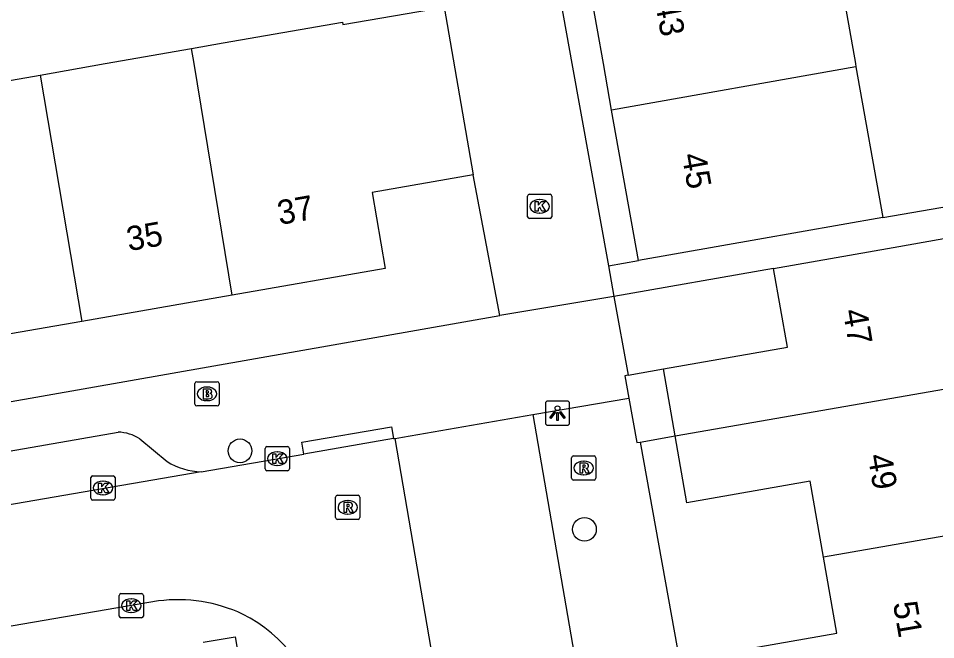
# Model space of a CAD drawing. Extents: x 162880 to 165536, y 384011 to 385179.
# Drawn here: x 164396.22 to 164434.07, y 384476.23 to 384501.87 of the extents above; entities that cross this region are included whole.
import ezdxf

# ---------------------------------------------------------------- set-up
doc = ezdxf.new("R2010")
doc.units = 0
for name, color, linetype in [('IMGEO_Boom', 7, 'Continuous'), ('IMGEO_Brandkraan', 7, 'Continuous'), ('IMGEO_Kolk', 7, 'Continuous'), ('IMGEO_Lichtpunt', 7, 'Continuous'), ('IMGEO_Pand', 7, 'Continuous'), ('IMGEO_Pand_nummerreeks', 7, 'Continuous'), ('IMGEO_Rijbaan_lokaal_open', 7, 'Continuous'), ('IMGEO_Rioolput', 7, 'Continuous'), ('IMGEO_Voetpad_open', 7, 'Continuous')]:
    doc.layers.add(name, color=color, linetype=linetype)

msp = doc.modelspace()

# ---------------------------------------------------------------- linework, layer by layer
at = {"layer": 'IMGEO_Boom'}
for centre in [(164405.369, 384484.024), (164419.578, 384480.785)]:
    msp.add_circle(centre, 0.489, dxfattribs=at)
at = {"layer": 'IMGEO_Brandkraan'}
for p, q in [((164403.581, 384486.875), (164404.433, 384486.875)), ((164403.506, 384485.949), (164403.506, 384486.801)), ((164403.994, 384486.655), (164404.019, 384486.655)), ((164404.507, 384486.801), (164404.507, 384485.949)), ((164404.017, 384486.095), (164403.992, 384486.095)), ((164404.433, 384485.875), (164403.581, 384485.875))]:
    msp.add_line(p, q, dxfattribs=at)
for points in [[(164403.581, 384486.875), (164404.433, 384486.875)], [(164403.506, 384485.949), (164403.506, 384486.801)], [(164403.854, 384486.575), (164403.854, 384486.175), (164404.067, 384486.175)], [(164404.085, 384486.575), (164403.854, 384486.575)], [(164404.033, 384486.494), (164403.979, 384486.494), (164403.979, 384486.418)], [(164404.507, 384486.801), (164404.507, 384485.949)], [(164403.979, 384486.418), (164404.032, 384486.418)], [(164404.041, 384486.342), (164403.979, 384486.342), (164403.979, 384486.261)], [(164403.979, 384486.261), (164404.041, 384486.261)], [(164404.433, 384485.875), (164403.581, 384485.875)]]:
    msp.add_lwpolyline(points, dxfattribs=at)
for centre, radius, start, end in [((164403.583, 384486.799), 0.0765, 91.552, 178.448), ((164403.583, 384486.799), 0.0765, 91.552, 178.448), ((164404.431, 384486.799), 0.0765, 1.552, 88.448), ((164404.431, 384486.799), 0.0765, 1.552, 88.448), ((164404.034, 384486.456), 0.0379, 267.8285, 90.9355), ((164404.089, 384486.43), 0.145, 59.4692, 91.5367), ((164404.114, 384486.477), 0.0922, 285.5137, 58.1501), ((164404.042, 384486.301), 0.0404, 269.8759, 90.5077), ((164404.073, 384486.426), 0.251, 268.6676, 293.5347), ((164404.119, 384486.285), 0.105, 301.3115, 78.989), ((164403.583, 384485.951), 0.0765, 181.552, 268.448), ((164403.583, 384485.951), 0.0765, 181.552, 268.448), ((164404.431, 384485.951), 0.0765, 271.552, 358.448), ((164404.431, 384485.951), 0.0765, 271.552, 358.448)]:
    msp.add_arc(centre, radius, start, end, dxfattribs=at)
for centre, major_axis, ratio, start_param, end_param in [((164403.993, 384486.375), (-0.387, 0.002), 0.722429, 4.712389, 7.853982), ((164404.018, 384486.375), (-0.39, 0.002), 0.717154, 1.570796, 4.712389)]:
    msp.add_ellipse(centre, major_axis=major_axis, ratio=ratio, start_param=start_param, end_param=end_param, dxfattribs=at)
at = {"layer": 'IMGEO_Kolk'}
for p, q in [((164417.231, 384493.683), (164417.231, 384494.535)), ((164417.306, 384494.609), (164418.158, 384494.609)), ((164418.232, 384494.535), (164418.232, 384493.683)), ((164417.719, 384494.389), (164417.744, 384494.389)), ((164417.742, 384493.829), (164417.717, 384493.829)), ((164418.158, 384493.609), (164417.306, 384493.609)), ((164406.482, 384484.201), (164407.334, 384484.201)), ((164406.407, 384483.275), (164406.407, 384484.127)), ((164406.895, 384483.981), (164406.92, 384483.981)), ((164407.408, 384484.127), (164407.408, 384483.275)), ((164407.334, 384483.201), (164406.482, 384483.201)), ((164406.918, 384483.421), (164406.893, 384483.421)), ((164399.215, 384482.068), (164399.215, 384482.92)), ((164399.29, 384482.994), (164400.142, 384482.994)), ((164399.703, 384482.774), (164399.728, 384482.774)), ((164400.216, 384482.92), (164400.216, 384482.068)), ((164400.142, 384481.994), (164399.29, 384481.994)), ((164399.726, 384482.214), (164399.701, 384482.214)), ((164400.383, 384477.209), (164400.383, 384478.061)), ((164400.458, 384478.135), (164401.31, 384478.135)), ((164400.871, 384477.915), (164400.896, 384477.915)), ((164401.384, 384478.061), (164401.384, 384477.209)), ((164401.31, 384477.135), (164400.458, 384477.135)), ((164400.894, 384477.355), (164400.869, 384477.355))]:
    msp.add_line(p, q, dxfattribs=at)
for points in [[(164417.231, 384493.683), (164417.231, 384494.535)], [(164417.306, 384494.609), (164418.158, 384494.609)], [(164418.232, 384494.535), (164418.232, 384493.683)], [(164417.552, 384494.309), (164417.675, 384494.309), (164417.675, 384494.158), (164417.805, 384494.309), (164417.969, 384494.309), (164417.823, 384494.158), (164417.976, 384493.909), (164417.824, 384493.909), (164417.739, 384494.073), (164417.675, 384494.006), (164417.675, 384493.909), (164417.552, 384493.909), (164417.552, 384494.309)], [(164418.158, 384493.609), (164417.306, 384493.609)], [(164406.482, 384484.201), (164407.334, 384484.201)], [(164406.407, 384483.275), (164406.407, 384484.127)], [(164406.728, 384483.901), (164406.851, 384483.901), (164406.851, 384483.75), (164406.981, 384483.901), (164407.145, 384483.901), (164406.999, 384483.75), (164407.152, 384483.501), (164407, 384483.501), (164406.915, 384483.665), (164406.851, 384483.598), (164406.851, 384483.501), (164406.728, 384483.501), (164406.728, 384483.901)], [(164407.408, 384484.127), (164407.408, 384483.275)], [(164407.334, 384483.201), (164406.482, 384483.201)], [(164399.215, 384482.068), (164399.215, 384482.92)], [(164399.29, 384482.994), (164400.142, 384482.994)], [(164399.536, 384482.694), (164399.659, 384482.694), (164399.659, 384482.543), (164399.789, 384482.694), (164399.953, 384482.694), (164399.807, 384482.543), (164399.96, 384482.294), (164399.808, 384482.294), (164399.723, 384482.458), (164399.659, 384482.391), (164399.659, 384482.294), (164399.536, 384482.294), (164399.536, 384482.694)], [(164400.216, 384482.92), (164400.216, 384482.068)], [(164400.142, 384481.994), (164399.29, 384481.994)], [(164400.383, 384477.209), (164400.383, 384478.061)], [(164400.458, 384478.135), (164401.31, 384478.135)], [(164400.704, 384477.835), (164400.827, 384477.835), (164400.827, 384477.684), (164400.957, 384477.835), (164401.121, 384477.835), (164400.975, 384477.684), (164401.128, 384477.435), (164400.976, 384477.435), (164400.891, 384477.599), (164400.827, 384477.532), (164400.827, 384477.435), (164400.704, 384477.435), (164400.704, 384477.835)], [(164401.384, 384478.061), (164401.384, 384477.209)], [(164401.31, 384477.135), (164400.458, 384477.135)]]:
    msp.add_lwpolyline(points, dxfattribs=at)
for centre, start, end in [((164417.308, 384494.533), 91.552, 178.448), ((164417.308, 384494.533), 91.552, 178.448), ((164418.156, 384494.533), 1.552, 88.448), ((164418.156, 384494.533), 1.552, 88.448), ((164417.308, 384493.685), 181.552, 268.448), ((164417.308, 384493.685), 181.552, 268.448), ((164418.156, 384493.685), 271.552, 358.448), ((164418.156, 384493.685), 271.552, 358.448), ((164406.484, 384484.125), 91.552, 178.448), ((164406.484, 384484.125), 91.552, 178.448), ((164407.332, 384484.125), 1.552, 88.448), ((164407.332, 384484.125), 1.552, 88.448), ((164406.484, 384483.277), 181.552, 268.448), ((164406.484, 384483.277), 181.552, 268.448), ((164407.332, 384483.277), 271.552, 358.448), ((164407.332, 384483.277), 271.552, 358.448), ((164399.292, 384482.918), 91.552, 178.448), ((164399.292, 384482.918), 91.552, 178.448), ((164400.14, 384482.918), 1.552, 88.448), ((164400.14, 384482.918), 1.552, 88.448), ((164399.292, 384482.07), 181.552, 268.448), ((164399.292, 384482.07), 181.552, 268.448), ((164400.14, 384482.07), 271.552, 358.448), ((164400.14, 384482.07), 271.552, 358.448), ((164400.46, 384478.059), 91.552, 178.448), ((164400.46, 384478.059), 91.552, 178.448), ((164401.308, 384478.059), 1.552, 88.448), ((164401.308, 384478.059), 1.552, 88.448), ((164400.46, 384477.211), 181.552, 268.448), ((164400.46, 384477.211), 181.552, 268.448), ((164401.308, 384477.211), 271.552, 358.448), ((164401.308, 384477.211), 271.552, 358.448)]:
    msp.add_arc(centre, 0.0765, start, end, dxfattribs=at)
for centre, major_axis, ratio, start_param, end_param in [((164417.718, 384494.109), (-0.387, 0.002), 0.722429, 4.712389, 7.853982), ((164417.743, 384494.109), (-0.39, 0.002), 0.717154, 1.570796, 4.712389), ((164406.894, 384483.701), (-0.387, 0.002), 0.722429, 4.712389, 7.853982), ((164406.919, 384483.701), (-0.39, 0.002), 0.717154, 1.570796, 4.712389), ((164399.702, 384482.494), (-0.387, 0.002), 0.722429, 4.712389, 7.853982), ((164399.727, 384482.494), (-0.39, 0.002), 0.717154, 1.570796, 4.712389), ((164400.87, 384477.635), (-0.387, 0.002), 0.722429, 4.712389, 7.853982), ((164400.895, 384477.635), (-0.39, 0.002), 0.717154, 1.570796, 4.712389)]:
    msp.add_ellipse(centre, major_axis=major_axis, ratio=ratio, start_param=start_param, end_param=end_param, dxfattribs=at)
at = {"layer": 'IMGEO_Lichtpunt'}
for p, q in [((164417.967, 384485.984), (164417.967, 384485.177)), ((164417.967, 384485.984), (164417.967, 384485.177)), ((164418.869, 384486.079), (164418.061, 384486.079)), ((164418.869, 384486.079), (164418.061, 384486.079)), ((164418.963, 384485.177), (164418.963, 384485.984)), ((164418.963, 384485.177), (164418.963, 384485.984)), ((164418.061, 384485.083), (164418.869, 384485.083)), ((164418.061, 384485.083), (164418.869, 384485.083))]:
    msp.add_line(p, q, dxfattribs=at)
for points in [[(164418.341, 384485.648), (164418.38, 384485.62), (164418.192, 384485.358), (164418.154, 384485.385), (164418.341, 384485.648)], [(164418.443, 384485.6), (164418.49, 384485.6), (164418.49, 384485.278), (164418.443, 384485.278), (164418.443, 384485.6)], [(164418.553, 384485.62), (164418.591, 384485.647), (164418.778, 384485.385), (164418.739, 384485.357), (164418.553, 384485.62)]]:
    msp.add_lwpolyline(points, dxfattribs=at)
msp.add_circle((164418.466, 384485.782), 0.0994, dxfattribs=at)
for centre, start, end in [((164418.061, 384485.984), 90, 180), ((164418.061, 384485.984), 90, 180), ((164418.869, 384485.984), 0, 90), ((164418.869, 384485.984), 0, 90), ((164418.061, 384485.177), 180, 270), ((164418.061, 384485.177), 180, 270), ((164418.869, 384485.177), 270, 0), ((164418.869, 384485.177), 270, 360)]:
    msp.add_arc(centre, 0.0946, start, end, dxfattribs=at)
at = {"layer": 'IMGEO_Pand'}
for points in [[(164429.66, 384506.189), (164430.757, 384500), (164430.78, 384499.872)], [(164420.701, 384498.076), (164420.358, 384500), (164419.576, 384504.392)], [(164403.369, 384500.623), (164404.674, 384500.851), (164409.6, 384501.707), (164409.617, 384501.608), (164413.785, 384502.333)], [(164413.785, 384502.333), (164414.981, 384495.409)], [(164397.123, 384499.529), (164399.812, 384500), (164403.369, 384500.623)], [(164405.044, 384490.444), (164403.472, 384500), (164403.369, 384500.623)], [(164430.78, 384499.872), (164420.701, 384498.076)], [(164430.78, 384499.872), (164431.883, 384493.646)], [(164390.868, 384498.434), (164397.123, 384499.529)], [(164397.123, 384499.529), (164398.839, 384489.366)], [(164421.805, 384491.877), (164420.701, 384498.076)], [(164414.981, 384495.409), (164410.814, 384494.685), (164411.356, 384491.541), (164405.044, 384490.444)], [(164431.883, 384493.646), (164426.73, 384492.742), (164421.805, 384491.877)], [(164427.38, 384491.551), (164432.311, 384492.416), (164436.257, 384493.109)], [(164422.835, 384487.402), (164427.95, 384488.299), (164427.38, 384491.551)], [(164405.044, 384490.444), (164398.839, 384489.366)], [(164398.839, 384489.366), (164392.632, 384488.287)], [(164421.377, 384487.147), (164422.835, 384487.402)], [(164423.32, 384484.64), (164422.835, 384487.402)], [(164421.377, 384487.147), (164421.248, 384487.124), (164421.411, 384486.193)], [(164423.32, 384484.64), (164437.315, 384487.079)], [(164421.411, 384486.193), (164421.733, 384484.363), (164421.873, 384484.387)], [(164421.873, 384484.387), (164423.32, 384484.64)], [(164429.44, 384479.638), (164428.889, 384482.775), (164423.804, 384481.882), (164423.32, 384484.64)], [(164438.349, 384481.19), (164429.44, 384479.638)], [(164425.375, 384472.85), (164424.891, 384475.606), (164429.99, 384476.501), (164429.44, 384479.638)]]:
    msp.add_lwpolyline(points, dxfattribs=at)
at = {"layer": 'IMGEO_Rijbaan_lokaal_open'}
for points in [[(164411.706, 384484.527), (164408, 384483.889)], [(164411.706, 384484.527), (164411.771, 384484.538)], [(164415.39, 384463.43), (164411.771, 384484.538)], [(164403.767, 384483.16), (164408, 384483.889)], [(164403.767, 384483.16), (164371.349, 384477.577)], [(164402.003, 384477.829), (164388.643, 384475.533)]]:
    msp.add_lwpolyline(points, dxfattribs=at)
for centre, radius, start, end in [((164402.811, 384471.636), 6.246, 64.7334, 97.4348), ((164402.895, 384472.041), 5.844, 8.3358, 63.7856)]:
    msp.add_arc(centre, radius, start, end, dxfattribs=at)
at = {"layer": 'IMGEO_Rioolput'}
for p, q in [((164419.122, 384483.816), (164419.974, 384483.816)), ((164419.047, 384482.89), (164419.047, 384483.742)), ((164419.535, 384483.596), (164419.56, 384483.596)), ((164420.048, 384483.742), (164420.048, 384482.89)), ((164419.974, 384482.816), (164419.122, 384482.816)), ((164419.558, 384483.036), (164419.533, 384483.036)), ((164409.312, 384481.267), (164409.312, 384482.119)), ((164409.387, 384482.193), (164410.239, 384482.193)), ((164409.8, 384481.973), (164409.825, 384481.973)), ((164410.313, 384482.119), (164410.313, 384481.267)), ((164410.239, 384481.193), (164409.387, 384481.193)), ((164409.823, 384481.413), (164409.798, 384481.413))]:
    msp.add_line(p, q, dxfattribs=at)
for points in [[(164419.122, 384483.816), (164419.974, 384483.816)], [(164419.047, 384482.89), (164419.047, 384483.742)], [(164419.636, 384483.514), (164419.384, 384483.516), (164419.384, 384483.116)], [(164420.048, 384483.742), (164420.048, 384482.89)], [(164419.384, 384483.116), (164419.508, 384483.116), (164419.508, 384483.278), (164419.519, 384483.278)], [(164419.562, 384483.435), (164419.508, 384483.435), (164419.508, 384483.354)], [(164419.508, 384483.354), (164419.56, 384483.354)], [(164419.566, 384483.249), (164419.637, 384483.116), (164419.777, 384483.116), (164419.712, 384483.242)], [(164419.974, 384482.816), (164419.122, 384482.816)], [(164409.312, 384481.267), (164409.312, 384482.119)], [(164409.387, 384482.193), (164410.239, 384482.193)], [(164410.313, 384482.119), (164410.313, 384481.267)], [(164409.901, 384481.891), (164409.649, 384481.893), (164409.649, 384481.493)], [(164409.649, 384481.493), (164409.773, 384481.493), (164409.773, 384481.655), (164409.784, 384481.655)], [(164409.827, 384481.812), (164409.773, 384481.812), (164409.773, 384481.731)], [(164409.773, 384481.731), (164409.825, 384481.731)], [(164409.831, 384481.626), (164409.902, 384481.493), (164410.042, 384481.493), (164409.977, 384481.619)], [(164410.239, 384481.193), (164409.387, 384481.193)]]:
    msp.add_lwpolyline(points, dxfattribs=at)
for centre, radius, start, end in [((164419.124, 384483.74), 0.0765, 91.552, 178.448), ((164419.124, 384483.74), 0.0765, 91.552, 178.448), ((164419.972, 384483.74), 0.0765, 1.552, 88.448), ((164419.972, 384483.74), 0.0765, 1.552, 88.448), ((164419.635, 384483.404), 0.109, 350.3612, 89.416), ((164419.518, 384483.225), 0.0533, 26.0293, 88.6989), ((164419.544, 384483.543), 0.19, 274.7715, 282.9687), ((164419.568, 384483.339), 0.0964, 77.0061, 93.1865), ((164419.582, 384483.396), 0.0378, 276.6634, 79.6772), ((164419.633, 384483.404), 0.112, 277.5842, 350.9817), ((164419.617, 384483.189), 0.108, 29.5134, 73.7905), ((164419.124, 384482.892), 0.0765, 181.552, 268.448), ((164419.124, 384482.892), 0.0765, 181.552, 268.448), ((164419.972, 384482.892), 0.0765, 271.552, 358.448), ((164419.972, 384482.892), 0.0765, 271.552, 358.448), ((164409.389, 384482.117), 0.0765, 91.552, 178.448), ((164409.389, 384482.117), 0.0765, 91.552, 178.448), ((164410.237, 384482.117), 0.0765, 1.552, 88.448), ((164410.237, 384482.117), 0.0765, 1.552, 88.448), ((164409.783, 384481.602), 0.0533, 26.0293, 88.6989), ((164409.809, 384481.92), 0.19, 274.7715, 282.9687), ((164409.833, 384481.716), 0.0964, 77.0061, 93.1865), ((164409.847, 384481.773), 0.0378, 276.6634, 79.6772), ((164409.9, 384481.781), 0.109, 350.3612, 89.416), ((164409.898, 384481.781), 0.112, 277.5842, 350.9817), ((164409.882, 384481.566), 0.108, 29.5134, 73.7905), ((164409.389, 384481.269), 0.0765, 181.552, 268.448), ((164409.389, 384481.269), 0.0765, 181.552, 268.448), ((164410.237, 384481.269), 0.0765, 271.552, 358.448), ((164410.237, 384481.269), 0.0765, 271.552, 358.448)]:
    msp.add_arc(centre, radius, start, end, dxfattribs=at)
for centre, major_axis, ratio, start_param, end_param in [((164419.534, 384483.316), (-0.387, 0.002), 0.722429, 4.712389, 7.853982), ((164419.559, 384483.316), (-0.39, 0.002), 0.717154, 1.570796, 4.712389), ((164409.799, 384481.693), (-0.387, 0.002), 0.722429, 4.712389, 7.853982), ((164409.824, 384481.693), (-0.39, 0.002), 0.717154, 1.570796, 4.712389)]:
    msp.add_ellipse(centre, major_axis=major_axis, ratio=ratio, start_param=start_param, end_param=end_param, dxfattribs=at)
at = {"layer": 'IMGEO_Voetpad_open'}
for points in [[(164411.342, 384515.842), (164411.329, 384515.915), (164416.06, 384516.684), (164419.063, 384500), (164420.565, 384491.656)], [(164416.085, 384489.611), (164414.981, 384495.409)], [(164431.883, 384493.646), (164440.745, 384495.183)], [(164420.565, 384491.656), (164421.805, 384491.877)], [(164420.565, 384491.656), (164420.792, 384490.396)], [(164427.38, 384491.551), (164420.792, 384490.396)], [(164420.792, 384490.396), (164416.085, 384489.611)], [(164420.792, 384490.396), (164421.377, 384487.147)], [(164341.812, 384476.692), (164368.416, 384481.213), (164416.085, 384489.611)], [(164417.448, 384485.519), (164421.411, 384486.193)], [(164411.771, 384484.538), (164412.072, 384484.59), (164417.448, 384485.519)], [(164417.448, 384485.519), (164422.583, 384455.77), (164418.958, 384455.119)], [(164408, 384483.889), (164407.916, 384484.381), (164411.622, 384485.019), (164411.706, 384484.527)], [(164370.988, 384479.683), (164400.338, 384484.794)], [(164401.238, 384484.514), (164402.358, 384483.58)], [(164421.873, 384484.387), (164427.236, 384454.587)], [(164403.85, 384476.13), (164405.175, 384476.35), (164412.939, 384431.091)]]:
    msp.add_lwpolyline(points, dxfattribs=at)
for centre, radius, start, end in [((164400.303, 384483.094), 1.701, 56.6303, 88.8067), ((164403.871, 384486.084), 2.926, 238.8498, 267.9533)]:
    msp.add_arc(centre, radius, start, end, dxfattribs=at)

# ---------------------------------------------------------------- texts
at = {"layer": 'IMGEO_Pand_nummerreeks'}
for s, rotation, p in [('43', 280.1726, (164422.488, 384502.527)), ('45', 280.1005, (164423.589, 384496.232)), ('37', 9.8577, (164407, 384493.342)), ('35', 9.8577, (164400.778, 384492.26)), ('47', 279.7287, (164430.237, 384489.803)), ('49', 279.7287, (164431.261, 384483.826)), ('51', 279.7287, (164432.305, 384477.739))]:
    msp.add_text(s, height=1, rotation=rotation, dxfattribs=at).set_placement(p)

doc.saveas('drawing.dxf')
